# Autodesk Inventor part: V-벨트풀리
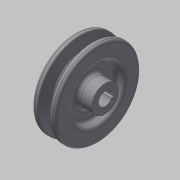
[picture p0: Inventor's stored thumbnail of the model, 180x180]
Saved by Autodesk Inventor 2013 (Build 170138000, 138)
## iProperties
Created: 2015-02
Part Number: V-벨트풀리
Material: 일반
Document SubType Name: Modeling
Designer: Administrator
Density: 1 g/cm^3
Author: Administrator
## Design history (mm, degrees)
sketch "스케치1"
  geometry: L1 (-9.5, 0)-(15.5, 0); L2 (-9.5, 5.5)-(-9.5, 11); L3 (-9.5, 11)-(-3.5, 11); L4 (-3.5, 11)-(-3.5, 21.5); L5 (-3.5, 21.5)-(-9.5, 21.5); L6 (-9.5, 21.5)-(-9.5, 35.2); L7 (-9.5, 35.2)-(-4.825, 35.2); L8 (-4.825, 35.2)-(-2.074, 26.2); L9 (-2.074, 26.2)-(2.074, 26.2); L10 (2.074, 26.2)-(4.825, 35.2); L11 (4.825, 35.2)-(9.5, 35.2); L12 (9.5, 35.2)-(9.5, 21.5); L13 (9.5, 21.5)-(3.5, 21.5); L14 (3.5, 21.5)-(3.5, 11); L15 (3.5, 11)-(15.5, 11); L16 (15.5, 11)-(15.5, 5.5); L17 (15.5, 5.5)-(-9.5, 5.5); L18 (-13.375, 32.5)-(22.907, 32.5); 4 further points
  constraints: 36 end point, 10 parallel, 5 collinear, 5 point on line, 4 vertical alignment, 2 perpendicular, 1 equal length, 1 horizontal, 1 midpoint, 1 vertical
  dimensions: "d0" = 25 distance of L1.start L1.end; "d2" = 9.5 distance of point (0, 0) L1.start; "d3" = 6 distance between parallel lines of L6 L4; "d4" = 19 distance between parallel lines of L12 L6; "d5" = 34 deg angle of L10 L8; "d6" = 11 diameter of L17 L1; "d8" = 43 diameter of L5 L1; "d9" = 22 diameter of L15 L1; "d11" = 6 distance between parallel lines of L14 L12; "d12" = 6.3 distance between parallel lines of L9 L18; "d13" = 2.7 distance between parallel lines of L18 L11; "d14" = 65 diameter of L18 L1; "d15" = 8 distance of point (-4, 32.5) point (4, 32.5)
revolve "회전1" sketch "스케치1" stored, may be unused: angle "d16" = 90 deg
fillet "모깎기1" dims "d17" = 2
fillet "모깎기2" dims "d18" = 1
fillet "모깎기3" dims "d19" = 0.5
fillet "모깎기4" dims "d20" = 3
sketch "스케치2"
  geometry: L1 (-2, 7.3)-(2, 7.3); L2 (2, 7.3)-(2, 5.123); L3 (-2, 7.3)-(-2, 5.123); A1 r 5.5 centre (0, 0) between (2, 5.123) and (-2, 5.123) reference; 1 further point
  constraints: 6 end point, 2 point on circle, 1 horizontal, 1 midpoint, 1 parallel, 1 perpendicular, 1 vertical alignment
  dimensions: "d21" = 4 distance of L1.start L1.end; "d23" = 12.8 dimension on A1 L1
extrude "돌출1" cut sketch "스케치2" stored distance "d24" = 10; taper "d25" = 0 deg
node "솔리드1"
